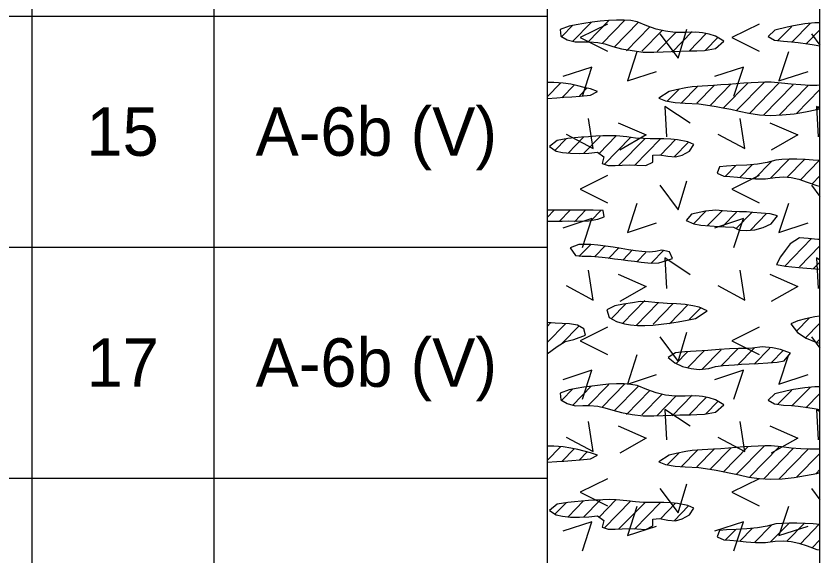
# Model space of a CAD drawing. Extents: x 0 to 0.833, y -0.32 to 0.608.
# Drawn here: x 0.7228 to 0.8333, y 0.1163 to 0.1905 of the extents above; entities that cross this region are included whole.
import ezdxf

# ---------------------------------------------------------------- set-up
doc = ezdxf.new("R2010")
doc.units = 0

msp = doc.modelspace()

# ---------------------------------------------------------------- linework, layer by layer
for points in [[(0, -0.32004), (0.83333, -0.32004), (0.83333, 0.60833), (0, 0.60833)], [(0.79885, 0.18911), (0.79763, 0.18865), (0.79773, 0.18776), (0.79859, 0.18723), (0.7997, 0.18694), (0.80074, 0.18695), (0.80165, 0.18696), (0.80281, 0.18688), (0.80377, 0.18667), (0.80486, 0.18632), (0.80606, 0.18602), (0.80751, 0.18575), (0.80905, 0.18556), (0.81052, 0.18553), (0.81177, 0.18559), (0.81289, 0.18563), (0.81408, 0.18567), (0.81553, 0.18571), (0.81642, 0.18573), (0.81745, 0.18576), (0.81897, 0.18604), (0.82011, 0.18707), (0.81896, 0.18774), (0.8181, 0.18801), (0.81717, 0.18821), (0.81626, 0.18831), (0.81479, 0.18825), (0.81343, 0.18826), (0.8121, 0.18841), (0.8108, 0.18871), (0.80953, 0.18917), (0.8082, 0.18972), (0.80736, 0.18988), (0.8064, 0.18995), (0.80536, 0.18995), (0.80427, 0.18989), (0.80314, 0.18978), (0.80201, 0.18964), (0.8009, 0.18947), (0.79984, 0.18929)], [(0.83263, 0.18956), (0.83126, 0.18942), (0.82969, 0.18916), (0.82883, 0.18898), (0.82712, 0.18857), (0.82623, 0.1877), (0.82708, 0.18721), (0.82831, 0.18703), (0.82941, 0.18696), (0.83033, 0.18687), (0.83165, 0.18669), (0.83253, 0.18655), (0.83333, 0.1864), (0.83333, 0.18955)], [(0.79583, 0.17916), (0.79715, 0.17927), (0.79814, 0.17934), (0.79922, 0.17942), (0.80039, 0.1795), (0.80179, 0.17962), (0.80275, 0.18014), (0.80179, 0.18048), (0.80091, 0.18069), (0.80003, 0.18092), (0.79909, 0.18112), (0.79803, 0.18129), (0.79677, 0.18138), (0.79583, 0.18136)], [(0.82816, 0.17691), (0.82978, 0.17708), (0.83137, 0.17733), (0.8329, 0.17764), (0.83333, 0.17775), (0.83333, 0.18099), (0.83295, 0.18095), (0.83188, 0.18098), (0.83071, 0.18103), (0.82938, 0.18113), (0.82807, 0.1813), (0.82662, 0.18142), (0.82576, 0.18142), (0.82484, 0.18139), (0.82387, 0.18134), (0.82286, 0.18127), (0.82182, 0.1812), (0.82077, 0.18111), (0.81973, 0.18103), (0.81872, 0.18095), (0.81715, 0.18086), (0.81579, 0.18077), (0.81491, 0.18063), (0.81357, 0.18036), (0.8126, 0.18014), (0.81121, 0.17923), (0.8121, 0.17886), (0.81345, 0.17862), (0.81479, 0.17853), (0.81668, 0.17843), (0.81818, 0.17823), (0.81905, 0.17808), (0.82, 0.1779), (0.82107, 0.17769), (0.82225, 0.17743), (0.82357, 0.17714), (0.82501, 0.17692), (0.82656, 0.17685)], [(0.79708, 0.17193), (0.79794, 0.17175), (0.79904, 0.17164), (0.80028, 0.1716), (0.80156, 0.17166), (0.80274, 0.17181), (0.80361, 0.17115), (0.80338, 0.17025), (0.80422, 0.16998), (0.80517, 0.16996), (0.80613, 0.17002), (0.8072, 0.17005), (0.80818, 0.17002), (0.80939, 0.16995), (0.81037, 0.17041), (0.81038, 0.17136), (0.8113, 0.17142), (0.81244, 0.17123), (0.81346, 0.17113), (0.81438, 0.17138), (0.81539, 0.17193), (0.81601, 0.17284), (0.81517, 0.17321), (0.81374, 0.17349), (0.81285, 0.17358), (0.81187, 0.17364), (0.81, 0.17364), (0.8091, 0.17366), (0.808, 0.17373), (0.80678, 0.17389), (0.8053, 0.17402), (0.80443, 0.17403), (0.80349, 0.17402), (0.80251, 0.17398), (0.80152, 0.17392), (0.80054, 0.17384), (0.79959, 0.17375), (0.7987, 0.17365), (0.79722, 0.17342), (0.79614, 0.17255)], [(0.83241, 0.17071), (0.83129, 0.17077), (0.83017, 0.17081), (0.8291, 0.17081), (0.82811, 0.17077), (0.82728, 0.17068), (0.82608, 0.17039), (0.82476, 0.17016), (0.8233, 0.17002), (0.82183, 0.16994), (0.82051, 0.16988), (0.81951, 0.16978), (0.81922, 0.16892), (0.82013, 0.1685), (0.82097, 0.16845), (0.822, 0.16835), (0.82318, 0.16822), (0.82448, 0.16813), (0.82584, 0.16815), (0.82719, 0.16832), (0.82836, 0.16839), (0.8294, 0.1683), (0.83043, 0.16807), (0.83156, 0.16768), (0.83291, 0.16719), (0.83333, 0.16711), (0.83333, 0.17063)], [(0.79583, 0.1623), (0.79676, 0.16229), (0.79792, 0.1623), (0.79882, 0.16234), (0.79992, 0.1623), (0.80151, 0.16234), (0.80282, 0.1626), (0.80367, 0.16292), (0.80354, 0.16376), (0.80216, 0.16384), (0.79583, 0.16384)], [(0.81822, 0.16165), (0.81944, 0.16159), (0.82033, 0.16155), (0.82145, 0.16148), (0.82229, 0.16107), (0.82324, 0.16103), (0.82438, 0.16113), (0.82555, 0.16142), (0.82662, 0.16192), (0.82749, 0.16302), (0.82651, 0.16332), (0.82524, 0.16342), (0.82413, 0.16349), (0.82324, 0.16359), (0.82226, 0.16361), (0.82121, 0.16364), (0.81995, 0.16373), (0.81902, 0.16384), (0.81761, 0.1637), (0.81566, 0.16326), (0.81496, 0.16242), (0.81598, 0.16193), (0.81695, 0.16176)], [(0.83305, 0.1598), (0.83171, 0.15991), (0.83054, 0.16001), (0.82925, 0.15919), (0.82857, 0.15828), (0.82792, 0.15739), (0.82735, 0.15636), (0.82858, 0.15614), (0.82945, 0.15604), (0.83045, 0.15594), (0.83155, 0.15584), (0.83272, 0.15575), (0.83333, 0.1557), (0.83333, 0.15979)], [(0.80066, 0.15749), (0.80188, 0.15749), (0.80339, 0.15736), (0.80423, 0.15726), (0.8051, 0.15715), (0.806, 0.15703), (0.80692, 0.15691), (0.80784, 0.15679), (0.80875, 0.15668), (0.81014, 0.15654), (0.81119, 0.15656), (0.81222, 0.1569), (0.81308, 0.15719), (0.81267, 0.15809), (0.8116, 0.15833), (0.81075, 0.15814), (0.80989, 0.15805), (0.80885, 0.15813), (0.80799, 0.15825), (0.80703, 0.15839), (0.806, 0.15855), (0.80492, 0.15872), (0.80384, 0.15888), (0.8028, 0.15901), (0.80182, 0.1591), (0.8002, 0.15911), (0.79901, 0.15864), (0.79974, 0.15759)], [(0.81233, 0.15099), (0.81063, 0.15111), (0.80977, 0.15124), (0.8086, 0.15125), (0.80755, 0.1511), (0.80632, 0.1509), (0.80513, 0.15066), (0.80403, 0.15014), (0.80436, 0.14908), (0.80536, 0.14851), (0.80647, 0.14821), (0.8073, 0.14806), (0.80824, 0.14799), (0.80926, 0.14798), (0.81035, 0.14803), (0.81149, 0.14813), (0.81267, 0.14828), (0.81386, 0.14846), (0.81506, 0.14868), (0.81625, 0.14891), (0.81783, 0.14999), (0.81673, 0.15049), (0.81585, 0.15069), (0.8148, 0.15085), (0.81361, 0.15095)], [(0.83265, 0.14918), (0.83136, 0.14887), (0.83028, 0.14859), (0.82934, 0.1482), (0.83026, 0.147), (0.83142, 0.14623), (0.83279, 0.14566), (0.83333, 0.14556), (0.83333, 0.14927)], [(0.79583, 0.14408), (0.79719, 0.14507), (0.79831, 0.14577), (0.79951, 0.14604), (0.80111, 0.14664), (0.80086, 0.14753), (0.80002, 0.148), (0.79889, 0.1482), (0.79791, 0.14823), (0.79694, 0.14828), (0.79583, 0.14837)], [(0.82537, 0.14502), (0.82408, 0.14487), (0.82319, 0.14482), (0.82214, 0.14479), (0.82091, 0.14475), (0.81947, 0.14466), (0.81792, 0.14454), (0.81632, 0.14442), (0.81475, 0.14433), (0.81348, 0.14423), (0.81247, 0.14359), (0.81337, 0.14283), (0.81444, 0.14232), (0.81561, 0.14204), (0.81675, 0.14193), (0.81807, 0.14204), (0.81896, 0.14232), (0.82003, 0.14246), (0.82157, 0.14258), (0.82253, 0.14264), (0.82362, 0.1427), (0.82483, 0.14276), (0.82618, 0.14283), (0.82745, 0.14294), (0.82842, 0.14311), (0.82927, 0.14417), (0.82791, 0.14468), (0.82679, 0.14488)], [(0.79885, 0.13911), (0.79763, 0.13865), (0.79773, 0.13776), (0.79859, 0.13723), (0.7997, 0.13694), (0.80074, 0.13695), (0.80165, 0.13696), (0.80281, 0.13688), (0.80377, 0.13667), (0.80486, 0.13632), (0.80606, 0.13602), (0.80751, 0.13575), (0.80905, 0.13556), (0.81052, 0.13553), (0.81177, 0.13559), (0.81289, 0.13563), (0.81408, 0.13567), (0.81553, 0.13571), (0.81642, 0.13573), (0.81745, 0.13576), (0.81897, 0.13604), (0.82011, 0.13707), (0.81896, 0.13774), (0.8181, 0.13801), (0.81717, 0.13821), (0.81626, 0.13831), (0.81479, 0.13825), (0.81343, 0.13826), (0.8121, 0.13841), (0.8108, 0.13871), (0.80953, 0.13917), (0.8082, 0.13972), (0.80736, 0.13988), (0.8064, 0.13995), (0.80536, 0.13995), (0.80427, 0.13989), (0.80314, 0.13978), (0.80201, 0.13964), (0.8009, 0.13947), (0.79984, 0.13929)], [(0.83263, 0.13956), (0.83126, 0.13942), (0.82969, 0.13916), (0.82883, 0.13898), (0.82712, 0.13857), (0.82623, 0.1377), (0.82708, 0.13721), (0.82831, 0.13703), (0.82941, 0.13696), (0.83033, 0.13687), (0.83165, 0.13669), (0.83253, 0.13655), (0.83333, 0.1364), (0.83333, 0.13955)], [(0.79583, 0.12916), (0.79715, 0.12927), (0.79814, 0.12934), (0.79922, 0.12942), (0.80039, 0.1295), (0.80179, 0.12962), (0.80275, 0.13014), (0.80179, 0.13048), (0.80091, 0.13069), (0.80003, 0.13092), (0.79909, 0.13112), (0.79803, 0.13129), (0.79677, 0.13138), (0.79583, 0.13136)], [(0.82816, 0.12691), (0.82978, 0.12708), (0.83137, 0.12733), (0.8329, 0.12764), (0.83333, 0.12775), (0.83333, 0.13099), (0.83295, 0.13095), (0.83188, 0.13098), (0.83071, 0.13103), (0.82938, 0.13113), (0.82807, 0.1313), (0.82662, 0.13142), (0.82576, 0.13142), (0.82484, 0.13139), (0.82387, 0.13134), (0.82286, 0.13127), (0.82182, 0.1312), (0.82077, 0.13111), (0.81973, 0.13103), (0.81872, 0.13095), (0.81715, 0.13086), (0.81579, 0.13077), (0.81491, 0.13063), (0.81357, 0.13036), (0.8126, 0.13015), (0.81121, 0.12923), (0.8121, 0.12886), (0.81345, 0.12862), (0.81479, 0.12853), (0.81668, 0.12843), (0.81818, 0.12823), (0.81905, 0.12808), (0.82, 0.1279), (0.82107, 0.12769), (0.82225, 0.12743), (0.82357, 0.12714), (0.82501, 0.12692), (0.82656, 0.12685)], [(0.79708, 0.12193), (0.79794, 0.12175), (0.79904, 0.12164), (0.80028, 0.1216), (0.80156, 0.12166), (0.80274, 0.12181), (0.80361, 0.12115), (0.80338, 0.12025), (0.80422, 0.11998), (0.80517, 0.11996), (0.80613, 0.12002), (0.8072, 0.12005), (0.80818, 0.12002), (0.80939, 0.11995), (0.81037, 0.12041), (0.81038, 0.12136), (0.8113, 0.12142), (0.81244, 0.12123), (0.81346, 0.12113), (0.81438, 0.12138), (0.81539, 0.12193), (0.81601, 0.12284), (0.81517, 0.12321), (0.81374, 0.12349), (0.81285, 0.12358), (0.81187, 0.12364), (0.81, 0.12364), (0.8091, 0.12366), (0.808, 0.12373), (0.80678, 0.12389), (0.8053, 0.12402), (0.80443, 0.12403), (0.80349, 0.12402), (0.80251, 0.12398), (0.80152, 0.12392), (0.80054, 0.12384), (0.79959, 0.12375), (0.7987, 0.12365), (0.79722, 0.12342), (0.79614, 0.12255)], [(0.83241, 0.12071), (0.83129, 0.12077), (0.83017, 0.12081), (0.8291, 0.12081), (0.82811, 0.12077), (0.82728, 0.12069), (0.82608, 0.12039), (0.82476, 0.12016), (0.8233, 0.12002), (0.82183, 0.11994), (0.82051, 0.11988), (0.81951, 0.11978), (0.81922, 0.11892), (0.82013, 0.1185), (0.82097, 0.11845), (0.822, 0.11835), (0.82318, 0.11822), (0.82448, 0.11813), (0.82584, 0.11815), (0.82719, 0.11832), (0.82836, 0.11839), (0.8294, 0.1183), (0.83043, 0.11807), (0.83156, 0.11768), (0.83291, 0.11719), (0.83333, 0.11711), (0.83333, 0.12063)]]:
    msp.add_lwpolyline(points, close=True)
for points in [[(0.725, 0.55417), (0.725, -0.27517)], [(0.75, 0.55417), (0.75, -0.27517)], [(0.75, 0.55417), (0.75, -0.27517)], [(0.79583, 0.55417), (0.79583, -0.27517)], [(0.725, 0.54167), (0.725, -0.27517)], [(0.83333, -0.27517), (0.83333, 0.50377)], [(0.70417, 0.1905), (0.725, 0.1905)], [(0.725, 0.1905), (0.75, 0.1905)], [(0.75, 0.1905), (0.79583, 0.1905)], [(0.79938, 0.18925), (0.79786, 0.1877)], [(0.79933, 0.18699), (0.80195, 0.18968)], [(0.80412, 0.18941), (0.80038, 0.18754), (0.80412, 0.18566)], [(0.80142, 0.18692), (0.8043, 0.18987)], [(0.80653, 0.18994), (0.8034, 0.18673)], [(0.80506, 0.18622), (0.8084, 0.18964)], [(0.80997, 0.18904), (0.80675, 0.18574)], [(0.82496, 0.18941), (0.82121, 0.18754), (0.82496, 0.18566)], [(0.82751, 0.1871), (0.82945, 0.18908)], [(0.83203, 0.18951), (0.82949, 0.18691)], [(0.81164, 0.18854), (0.80884, 0.18567)], [(0.81353, 0.18826), (0.81094, 0.18561)], [(0.81134, 0.18807), (0.81384, 0.1847), (0.81503, 0.1887)], [(0.81303, 0.18554), (0.81579, 0.18837)], [(0.81534, 0.18569), (0.81768, 0.18809)], [(0.83138, 0.18663), (0.83333, 0.18863)], [(0.83217, 0.18807), (0.83333, 0.18651)], [(0.8176, 0.1858), (0.81934, 0.18758)], [(0.83333, 0.18642), (0.83333, 0.18642)], [(0.80818, 0.18558), (0.80687, 0.18158), (0.81087, 0.1829)], [(0.82901, 0.18558), (0.8277, 0.18158), (0.8317, 0.1829)], [(0.80069, 0.1795), (0.802, 0.1835), (0.798, 0.18219)], [(0.82152, 0.1795), (0.82284, 0.1835), (0.81884, 0.18219)], [(0.79765, 0.18127), (0.79583, 0.1794)], [(0.82004, 0.17783), (0.82346, 0.18133)], [(0.82569, 0.18141), (0.82184, 0.17747)], [(0.82775, 0.18131), (0.8237, 0.17716)], [(0.7996, 0.18105), (0.79786, 0.17927)], [(0.8013, 0.18057), (0.80027, 0.17952)], [(0.81392, 0.18042), (0.81235, 0.17881)], [(0.8143, 0.17859), (0.8165, 0.18084)], [(0.8164, 0.17852), (0.81879, 0.18098)], [(0.81829, 0.17825), (0.82114, 0.18117)], [(0.82964, 0.18104), (0.82557, 0.17686)], [(0.83173, 0.18097), (0.82774, 0.17688)], [(0.83333, 0.18039), (0.83012, 0.1771)], [(0.81551, 0.17578), (0.81201, 0.17809), (0.81226, 0.1739)], [(0.83281, 0.17764), (0.83333, 0.17818)], [(0.83333, 0.17777), (0.83284, 0.17809), (0.83309, 0.1739)], [(0.79847, 0.17429), (0.80215, 0.17229), (0.80153, 0.17642)], [(0.80562, 0.17584), (0.80946, 0.17416), (0.80581, 0.17209)], [(0.8193, 0.17429), (0.82299, 0.17229), (0.82236, 0.17642)], [(0.82645, 0.17584), (0.83029, 0.17416), (0.82664, 0.17209)], [(0.79844, 0.17361), (0.79691, 0.17204)], [(0.79871, 0.17167), (0.80085, 0.17386)], [(0.80083, 0.17163), (0.80311, 0.17397)], [(0.80534, 0.17404), (0.80299, 0.17163)], [(0.80367, 0.17011), (0.80732, 0.17385)], [(0.80571, 0.17), (0.80924, 0.17361)], [(0.81142, 0.17363), (0.80785, 0.16997)], [(0.81141, 0.1714), (0.81348, 0.17353)], [(0.81528, 0.17316), (0.81331, 0.17114)], [(0.82433, 0.16814), (0.82666, 0.17053)], [(0.82909, 0.17081), (0.82656, 0.16822)], [(0.82885, 0.16835), (0.83122, 0.17078)], [(0.83325, 0.17064), (0.83065, 0.16798)], [(0.82035, 0.16849), (0.82176, 0.16994)], [(0.82233, 0.16831), (0.82408, 0.1701)], [(0.80412, 0.16858), (0.80038, 0.16671), (0.80412, 0.16483)], [(0.82496, 0.16858), (0.82121, 0.16671), (0.82496, 0.16483)], [(0.83333, 0.16852), (0.83227, 0.16742)], [(0.81134, 0.16724), (0.81384, 0.16387), (0.81503, 0.16787)], [(0.83217, 0.16724), (0.83333, 0.16568)], [(0.80818, 0.16475), (0.80687, 0.16075), (0.81087, 0.16206)], [(0.82901, 0.16475), (0.8277, 0.16075), (0.8317, 0.16206)], [(0.79583, 0.16281), (0.79681, 0.16381)], [(0.79898, 0.16383), (0.79747, 0.16228)], [(0.80116, 0.16385), (0.79959, 0.16224)], [(0.80328, 0.16381), (0.80188, 0.16238)], [(0.8177, 0.16371), (0.81596, 0.16192)], [(0.81988, 0.16373), (0.81785, 0.16165)], [(0.80069, 0.15867), (0.802, 0.16267), (0.798, 0.16136)], [(0.82152, 0.15867), (0.82284, 0.16267), (0.81884, 0.16136)], [(0.82185, 0.16354), (0.81997, 0.16161)], [(0.824, 0.16353), (0.82178, 0.16125)], [(0.82601, 0.16337), (0.82378, 0.16109)], [(0.80188, 0.15915), (0.8002, 0.15743)], [(0.83217, 0.15992), (0.82844, 0.1561)], [(0.70417, 0.15875), (0.725, 0.15875)], [(0.725, 0.15875), (0.75, 0.15875)], [(0.75, 0.15875), (0.79583, 0.15875)], [(0.8038, 0.1589), (0.80237, 0.15744)], [(0.80575, 0.15869), (0.80429, 0.1572)], [(0.80758, 0.15835), (0.80627, 0.15701)], [(0.80941, 0.15802), (0.80816, 0.15674)], [(0.81188, 0.15833), (0.81016, 0.15658)], [(0.83333, 0.1589), (0.83052, 0.15602)], [(0.81551, 0.15494), (0.81201, 0.15726), (0.81226, 0.15307)], [(0.83333, 0.15693), (0.83284, 0.15726), (0.83309, 0.15307)], [(0.83333, 0.15669), (0.83245, 0.15579)], [(0.79847, 0.15346), (0.80215, 0.15146), (0.80153, 0.15559)], [(0.80562, 0.15501), (0.80946, 0.15332), (0.80581, 0.15126)], [(0.8193, 0.15346), (0.82299, 0.15146), (0.82236, 0.15559)], [(0.82645, 0.15501), (0.83029, 0.15332), (0.82664, 0.15126)], [(0.80626, 0.1483), (0.80928, 0.1514)], [(0.80465, 0.14887), (0.80667, 0.15095)], [(0.80809, 0.14797), (0.81111, 0.15107)], [(0.81041, 0.14814), (0.81318, 0.15097)], [(0.81264, 0.14821), (0.81518, 0.15081)], [(0.81536, 0.14878), (0.81699, 0.15045)], [(0.7963, 0.14833), (0.79583, 0.14784)], [(0.79834, 0.1482), (0.79583, 0.14563)], [(0.8301, 0.14721), (0.83184, 0.14899)], [(0.83131, 0.14623), (0.83333, 0.14831)], [(0.79786, 0.1455), (0.80023, 0.14792)], [(0.80412, 0.14775), (0.80038, 0.14587), (0.80412, 0.144)], [(0.81134, 0.14641), (0.81384, 0.14303), (0.81503, 0.14703)], [(0.82496, 0.14775), (0.82121, 0.14587), (0.82496, 0.144)], [(0.83217, 0.14641), (0.83333, 0.14485)], [(0.83285, 0.14561), (0.83333, 0.1461)], [(0.8197, 0.14237), (0.82203, 0.14477)], [(0.82202, 0.14253), (0.8243, 0.14487)], [(0.82431, 0.14267), (0.82644, 0.14486)], [(0.80818, 0.14392), (0.80687, 0.13992), (0.81087, 0.14123)], [(0.81519, 0.14439), (0.81354, 0.1427)], [(0.81514, 0.14213), (0.81748, 0.14453)], [(0.81709, 0.14191), (0.81974, 0.14463)], [(0.82663, 0.14283), (0.82834, 0.14458)], [(0.82901, 0.14392), (0.8277, 0.13992), (0.8317, 0.14123)], [(0.80069, 0.13784), (0.802, 0.14184), (0.798, 0.14052)], [(0.82152, 0.13784), (0.82284, 0.14184), (0.81884, 0.14052)], [(0.79938, 0.13925), (0.79786, 0.1377)], [(0.79933, 0.13699), (0.80195, 0.13968)], [(0.80142, 0.13692), (0.8043, 0.13987)], [(0.80653, 0.13994), (0.8034, 0.13673)], [(0.80506, 0.13622), (0.8084, 0.13964)], [(0.83203, 0.13951), (0.82949, 0.13691)], [(0.80997, 0.13904), (0.80675, 0.13574)], [(0.81164, 0.13854), (0.80884, 0.13567)], [(0.81353, 0.13826), (0.81094, 0.13561)], [(0.81303, 0.13554), (0.81579, 0.13837)], [(0.82751, 0.1371), (0.82945, 0.13908)], [(0.83138, 0.13663), (0.83333, 0.13863)], [(0.81534, 0.13569), (0.81768, 0.13809)], [(0.8176, 0.1358), (0.81934, 0.13758)], [(0.81551, 0.13411), (0.81201, 0.13642), (0.81226, 0.13223)], [(0.83333, 0.1361), (0.83284, 0.13642), (0.83309, 0.13223)], [(0.83333, 0.13642), (0.83333, 0.13642)], [(0.79847, 0.13263), (0.80215, 0.13063), (0.80153, 0.13475)], [(0.80562, 0.13417), (0.80946, 0.13249), (0.80581, 0.13043)], [(0.8193, 0.13263), (0.82299, 0.13063), (0.82236, 0.13475)], [(0.82645, 0.13417), (0.83029, 0.13249), (0.82664, 0.13043)], [(0.79765, 0.13127), (0.79583, 0.1294)], [(0.7996, 0.13105), (0.79786, 0.12927)], [(0.8013, 0.13057), (0.80027, 0.12952)], [(0.81392, 0.13042), (0.81235, 0.12881)], [(0.8143, 0.12859), (0.8165, 0.13084)], [(0.8164, 0.12852), (0.81879, 0.13098)], [(0.81829, 0.12825), (0.82114, 0.13117)], [(0.82004, 0.12783), (0.82346, 0.13133)], [(0.82569, 0.13141), (0.82184, 0.12747)], [(0.82775, 0.13131), (0.8237, 0.12716)], [(0.82964, 0.13104), (0.82557, 0.12686)], [(0.83173, 0.13097), (0.82774, 0.12688)], [(0.83333, 0.13039), (0.83012, 0.1271)], [(0.83281, 0.12764), (0.83333, 0.12818)], [(0.70417, 0.127), (0.725, 0.127)], [(0.725, 0.127), (0.75, 0.127)], [(0.75, 0.127), (0.79583, 0.127)], [(0.80412, 0.12691), (0.80038, 0.12504), (0.80412, 0.12316)], [(0.81134, 0.12557), (0.81384, 0.1222), (0.81503, 0.1262)], [(0.82496, 0.12691), (0.82121, 0.12504), (0.82496, 0.12316)], [(0.83217, 0.12557), (0.83333, 0.12401)], [(0.79871, 0.12167), (0.80085, 0.12386)], [(0.80083, 0.12163), (0.80311, 0.12397)], [(0.80534, 0.12404), (0.80299, 0.12163)], [(0.80367, 0.12011), (0.80732, 0.12385)], [(0.79844, 0.12361), (0.79691, 0.12204)], [(0.80571, 0.12), (0.80924, 0.12361)], [(0.80818, 0.12308), (0.80687, 0.11908), (0.81087, 0.1204)], [(0.81142, 0.12363), (0.80785, 0.11997)], [(0.81141, 0.1214), (0.81348, 0.12353)], [(0.81528, 0.12316), (0.81331, 0.12114)], [(0.82901, 0.12308), (0.8277, 0.11908), (0.8317, 0.1204)], [(0.80069, 0.117), (0.802, 0.121), (0.798, 0.11969)], [(0.82152, 0.117), (0.82284, 0.121), (0.81884, 0.11969)], [(0.82433, 0.11814), (0.82666, 0.12053)], [(0.82909, 0.12081), (0.82656, 0.11822)], [(0.82885, 0.11835), (0.83122, 0.12078)], [(0.83325, 0.12064), (0.83065, 0.11798)], [(0.82035, 0.11849), (0.82176, 0.11994)], [(0.82233, 0.11831), (0.82408, 0.1201)], [(0.83333, 0.11852), (0.83227, 0.11742)]]:
    msp.add_lwpolyline(points)

# ---------------------------------------------------------------- texts
for s, p in [('15', (0.73251, 0.17129)), ('A-6b (V)', (0.75575, 0.17129)), ('17', (0.73253, 0.13954)), ('A-6b (V)', (0.75575, 0.13954))]:
    msp.add_text(s, height=0.006667).set_placement(p)

doc.saveas('drawing.dxf')
